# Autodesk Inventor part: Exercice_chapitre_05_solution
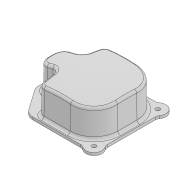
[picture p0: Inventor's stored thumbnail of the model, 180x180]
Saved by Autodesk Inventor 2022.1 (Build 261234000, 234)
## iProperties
Created: 2019-12
Part Number: Exercice_chapitre_05_solution
Material: Générique
Document SubType Name: Modeling
Designer: Fabian
Density: 1 g/cm^3
Appearance: Par défaut
Mass: 148.889 g
Surface Area: 905.766 cm^2
Volume: 148.889 cm^3
Author: Fabian
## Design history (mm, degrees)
sketch "Esquisse1"
  geometry: L1 (0, 70)-(0, -66.117); L2 (90, 0)-(-70, 0); L3 (90, 14.325)-(90, 0); L4 (-70, 45)-(-70, 0); L5 (44.578, 70)-(-45, 70); L6 (86.745, 24.649)-(60.961, 61.472); L7 (83, 0)-(83, 5); L8 (65, 23)-(55, 23); L9 (43, 35)-(43, 51); L10 (31, 63)-(-18, 63); L11 (-63, 18)-(-63, 0); L12 (-63, -18)-(-63, 0); L13 (0, -70)-(0, 66.117); L14 (-70, -45)-(-70, 0); L15 (31, -63)-(-18, -63); L16 (44.578, -70)-(-45, -70); L17 (43, -35)-(43, -51); L18 (90, -14.325)-(90, 0); L19 (86.745, -24.649)-(60.961, -61.472); L20 (83, 0)-(83, -5); L21 (65, -23)-(55, -23); C1 r 4 at (-60, 60); C2 r 6 at (55, 35); C3 r 4 at (-60, -60); C4 r 6 at (55, -35); A1 r 15 centre (-60, 60) between (-51, 72) and (-72, 51); A2 r 12 centre (55, 35) between (43, 35) and (55, 23); A3 r 12 centre (31, 51) between (43, 51) and (31, 63); A4 r 18 centre (72, 14.325) between (90, 14.325) and (86.745, 24.649); A5 r 20 centre (44.578, 50) between (60.961, 61.472) and (44.578, 70); A6 r 10 centre (-45, 80) between (-51, 72) and (-45, 70); A7 r 10 centre (-80, 45) between (-70, 45) and (-72, 51); A8 r 18 centre (65, 5) between (83, 5) and (65, 23); A9 r 45 centre (-18, 18) between (-18, 63) and (-63, 18); A10 r 45 centre (-18, -18) between (-63, -18) and (-18, -63); A11 r 12 centre (31, -51) between (31, -63) and (43, -51); A12 r 10 centre (-45, -80) between (-45, -70) and (-51, -72); A13 r 15 centre (-60, -60) between (-72, -51) and (-51, -72); A14 r 10 centre (-80, -45) between (-72, -51) and (-70, -45); A15 r 12 centre (55, -35) between (55, -23) and (43, -35); A16 r 20 centre (44.578, -50) between (44.578, -70) and (60.961, -61.472); A17 r 18 centre (65, -5) between (65, -23) and (83, -5); A18 r 18 centre (72, -14.325) between (86.745, -24.649) and (90, -14.325); 7 further points
  constraints: 44 end point, 40 point on circle, 32 symmetric about line, 22 centre point, 16 tangent, 14 point on line, 5 perpendicular, 4 coincident, 3 vertical, 2 horizontal, 11 other
  dimensions: "d2" = 70 distance between parallel lines of L4 L1; "d3" = 90 distance between parallel lines of L3 L1; "d5" = 30 diameter of A1; "d6" = 140 diameter of L5 L2; "d7" = 20 distance of point (90, 20) L2.start; "d8" = 35 deg angle of L3 L6; "d9" = 120 diameter of A1.centre L2; "d11" = 60 distance from line of A1.centre L1; "d12" = 8 diameter of C1; "d13" = 70 diameter of C2.centre L2; "d14" = 55 distance from line of C2.centre L1; "d15" = 12 diameter of C2; "d16" = 83 distance between parallel lines of L7 L1; "d17" = 63 distance between parallel lines of L11 L1; "d18" = 46 diameter of L8 L2 (derived); "d19" = 126 diameter of L10 L2; "d21" = 12 radius of A2; "d22" = 43 distance between parallel lines of L9 L1 (derived); "d23" = 12 radius of A3 (derived); "d24" = 18 radius of A4 (derived); "d25" = 20 radius of A5; "d26" = 10 radius of A6; "d27" = 10 radius of A7; "d28" = 18 radius of A8; "d29" = 45 radius of A9
extrude "Extrusion1" new body sketch "Esquisse1" distance "d30" = 65; taper "d31" = -1 deg
sketch "Esquisse2"
  geometry: L1 (-81.865, 65)-(61.865, 65); L2 (0, -455)-(0, 65); L3 (18, 65)-(-31, 65) reference; L4 (-55, 65)-(-65, 65) reference; A1 r 260 centre (0, -195) between (0, -455) and (0, 65); 1 further point
  constraints: 4 end point, 2 point on circle, 1 centre point, 1 collinear, 1 point on line, 1 tangent, 1 vertical, 1 vertical alignment
  dimensions: "d32" = 520 diameter of A1
revolve "Révolution1" sketch "Esquisse2" stored, may be unused: angle "d33" = 90 deg
fillet "Congé1" dims "d36" = 5
feature "Coque1" dims "d37" = 3
extrude "Extrusion2" join sketch "Esquisse1" distance "d34" = 5; taper "d35" = 0 deg
fillet "Congé2" dims "d38" = 5
node "Solide1"
